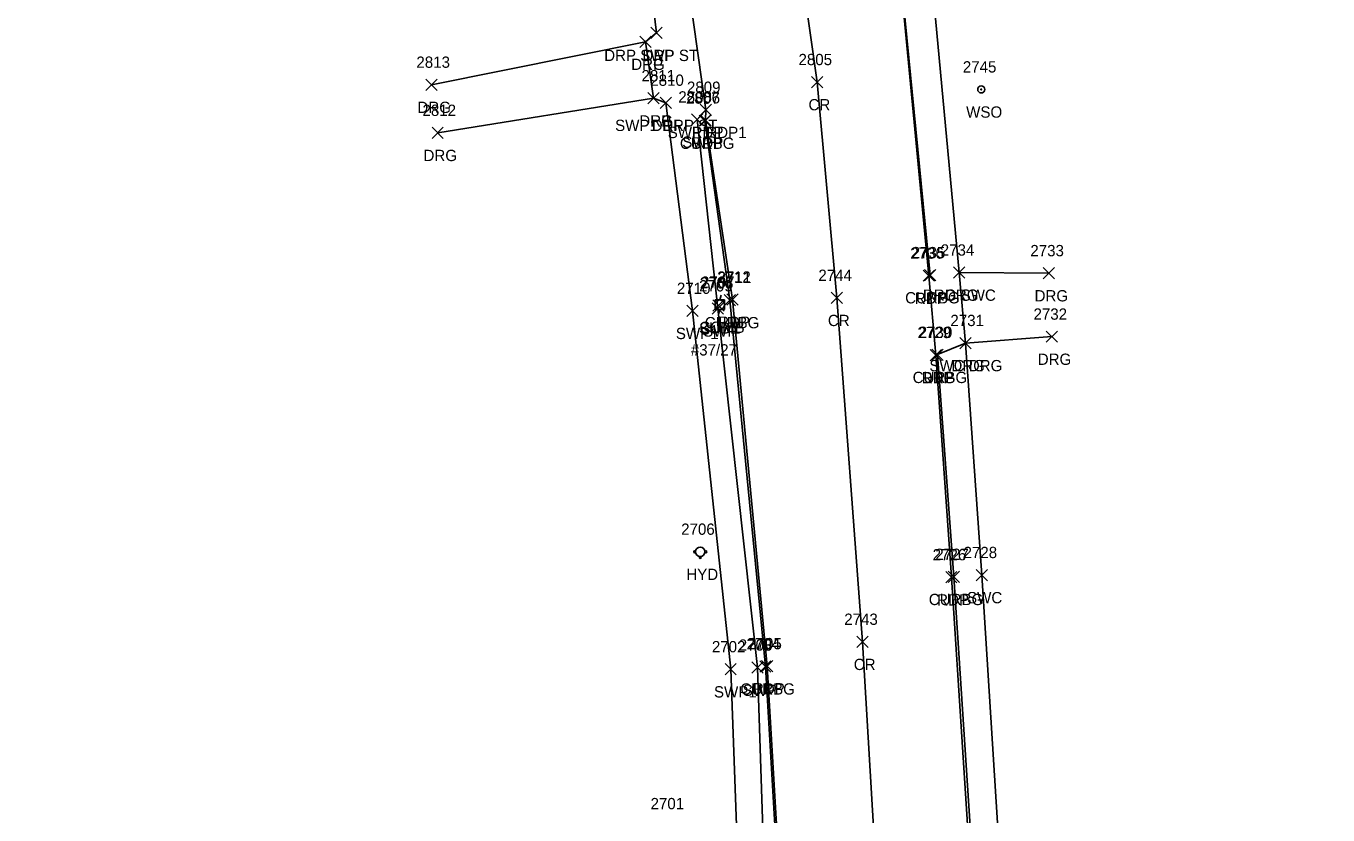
# Model space of a CAD drawing. Extents: x 1690689 to 1696275, y 438760 to 444007.
# Drawn here: x 1691078.4 to 1691309, y 441527.3 to 441667 of the extents above; entities that cross this region are included whole.
import ezdxf

# ---------------------------------------------------------------- set-up
doc = ezdxf.new("R2010")
doc.units = 0
for name, color, linetype in [('L_I', 7, 'Continuous'), ('P_A', 7, 'Continuous'), ('P_I', 7, 'Continuous'), ('P_TIC', 7, 'Continuous'), ('PET', 7, 'Continuous'), ('PRC', 7, 'Continuous'), ('R_A', 7, 'Continuous'), ('R_I', 7, 'Continuous'), ('R_TIC', 7, 'Continuous'), ('RC', 7, 'Continuous'), ('RDG', 7, 'Continuous'), ('RDP', 7, 'Continuous'), ('RSW', 7, 'Continuous'), ('U_A', 7, 'Continuous'), ('U_C', 7, 'Continuous'), ('U_I', 7, 'Continuous'), ('U_TIC', 7, 'Continuous'), ('UP', 7, 'Continuous'), ('UWFH', 7, 'Continuous'), ('UWV', 7, 'Continuous')]:
    doc.layers.add(name, color=color, linetype=linetype)

msp = doc.modelspace()

# ---------------------------------------------------------------- linework, layer by layer
at = {"layer": 'P_TIC'}
for points in [[(1691217.57, 441656.04), (1691219.57, 441658.04)], [(1691219.57, 441656.04), (1691217.57, 441658.04)], [(1691197.8, 441649.27), (1691199.8, 441651.27)], [(1691199.8, 441649.27), (1691197.8, 441651.27)], [(1691197.82, 441651.13), (1691199.82, 441653.13)], [(1691199.82, 441651.13), (1691197.82, 441653.13)], [(1691237.35, 441621.76), (1691239.35, 441623.76)], [(1691239.35, 441621.76), (1691237.35, 441623.76)], [(1691202.53, 441617.53), (1691204.53, 441619.53)], [(1691204.53, 441617.53), (1691202.53, 441619.53)], [(1691221.02, 441617.83), (1691223.02, 441619.83)], [(1691223.02, 441617.83), (1691221.02, 441619.83)], [(1691238.58, 441607.7), (1691240.58, 441609.7)], [(1691240.58, 441607.7), (1691238.58, 441609.7)], [(1691241.31, 441568.35), (1691243.31, 441570.35)], [(1691243.31, 441568.35), (1691241.31, 441570.35)], [(1691225.6, 441556.92), (1691227.6, 441558.92)], [(1691227.6, 441556.92), (1691225.6, 441558.92)], [(1691208.68, 441552.6), (1691210.68, 441554.6)], [(1691210.68, 441552.6), (1691208.68, 441554.6)]]:
    msp.add_lwpolyline(points, dxfattribs=at)
at = {"layer": 'PET'}
for points in [[(1691238.51, 441080.26), (1691233.04, 441128.02), (1691229.34, 441189.95), (1691225.2, 441266.32), (1691222.49, 441331.42), (1691221.87, 441352.01), (1691219.29, 441402.36), (1691215.78, 441404.57), (1691214.66, 441461.76), (1691212.86, 441499.57), (1691209.68, 441553.6), (1691203.53, 441618.53), (1691198.8, 441650.27), (1691198.82, 441652.13), (1691193.05, 441693.14)], [(1691309.01, 441068.57), (1691294.14, 441127.58), (1691279.71, 441186.12), (1691271.54, 441225.45), (1691269.6, 441237.09), (1691266.18, 441258.66), (1691260.33, 441297.66), (1691253.06, 441350.59), (1691250.02, 441376.37), (1691249.19, 441394.8), (1691248.99, 441398.05), (1691250.15, 441432.81), (1691248.61, 441468.02), (1691245.58, 441519.21), (1691242.31, 441569.35), (1691239.58, 441608.7), (1691238.35, 441622.76), (1691233.07, 441677.78)]]:
    msp.add_lwpolyline(points, dxfattribs=at)
at = {"layer": 'PRC'}
msp.add_lwpolyline([(1691277.81, 441080.96), (1691253.5, 441214.94), (1691246.19, 441267.52), (1691239.79, 441327.83), (1691235.79, 441375.29), (1691233.27, 441422.2), (1691229.73, 441505.18), (1691226.6, 441557.92), (1691222.02, 441618.83), (1691218.57, 441657.04), (1691144.02, 442182.42), (1691112.43, 442376.83), (1691097.75, 442454.48), (1691089.73, 442499.13), (1691078.44, 442565.84)], dxfattribs=at)
at = {"layer": 'R_TIC'}
for points in [[(1691187.13, 441663.19), (1691189.13, 441665.19)], [(1691189.13, 441663.19), (1691187.13, 441665.19)], [(1691187.13, 441663.19), (1691189.13, 441665.19)], [(1691189.13, 441663.19), (1691187.13, 441665.19)], [(1691189.11, 441664.77), (1691191.11, 441666.77)], [(1691191.11, 441664.77), (1691189.11, 441666.77)], [(1691189.11, 441664.77), (1691191.11, 441666.77)], [(1691191.11, 441664.77), (1691189.11, 441666.77)], [(1691149.27, 441655.57), (1691151.27, 441657.57)], [(1691151.27, 441655.57), (1691149.27, 441657.57)], [(1691188.56, 441653.17), (1691190.56, 441655.17)], [(1691190.56, 441653.17), (1691188.56, 441655.17)], [(1691188.56, 441653.17), (1691190.56, 441655.17)], [(1691190.56, 441653.17), (1691188.56, 441655.17)], [(1691190.76, 441652.38), (1691192.76, 441654.38)], [(1691192.76, 441652.38), (1691190.76, 441654.38)], [(1691190.76, 441652.38), (1691192.76, 441654.38)], [(1691192.76, 441652.38), (1691190.76, 441654.38)], [(1691196.3, 441649.42), (1691198.3, 441651.42)], [(1691198.3, 441649.42), (1691196.3, 441651.42)], [(1691197.66, 441649.21), (1691199.66, 441651.21)], [(1691199.66, 441649.21), (1691197.66, 441651.21)], [(1691197.82, 441651.13), (1691199.82, 441653.13)], [(1691199.82, 441651.13), (1691197.82, 441653.13)], [(1691150.34, 441647.05), (1691152.34, 441649.05)], [(1691152.34, 441647.05), (1691150.34, 441649.05)], [(1691237.55, 441621.85), (1691239.55, 441623.85)], [(1691239.55, 441621.85), (1691237.55, 441623.85)], [(1691242.69, 441622.31), (1691244.69, 441624.31)], [(1691244.69, 441622.31), (1691242.69, 441624.31)], [(1691242.69, 441622.31), (1691244.69, 441624.31)], [(1691244.69, 441622.31), (1691242.69, 441624.31)], [(1691258.56, 441622.2), (1691260.56, 441624.2)], [(1691260.56, 441622.2), (1691258.56, 441624.2)], [(1691202.06, 441617.44), (1691204.06, 441619.44)], [(1691204.06, 441617.44), (1691202.06, 441619.44)], [(1691195.48, 441615.53), (1691197.48, 441617.53)], [(1691197.48, 441615.53), (1691195.48, 441617.53)], [(1691199.98, 441615.97), (1691201.98, 441617.97)], [(1691201.98, 441615.97), (1691199.98, 441617.97)], [(1691243.84, 441609.83), (1691245.84, 441611.83)], [(1691245.84, 441609.83), (1691243.84, 441611.83)], [(1691243.84, 441609.83), (1691245.84, 441611.83)], [(1691245.84, 441609.83), (1691243.84, 441611.83)], [(1691259.12, 441610.96), (1691261.12, 441612.96)], [(1691261.12, 441610.96), (1691259.12, 441612.96)], [(1691238.58, 441607.7), (1691240.58, 441609.7)], [(1691240.58, 441607.7), (1691238.58, 441609.7)], [(1691238.88, 441607.74), (1691240.88, 441609.74)], [(1691240.88, 441607.74), (1691238.88, 441609.74)], [(1691241.73, 441568.42), (1691243.73, 441570.42)], [(1691243.73, 441568.42), (1691241.73, 441570.42)], [(1691246.73, 441568.74), (1691248.73, 441570.74)], [(1691248.73, 441568.74), (1691246.73, 441570.74)], [(1691202.23, 441552.06), (1691204.23, 441554.06)], [(1691204.23, 441552.06), (1691202.23, 441554.06)], [(1691207, 441552.35), (1691209, 441554.35)], [(1691209, 441552.35), (1691207, 441554.35)], [(1691208.37, 441552.57), (1691210.37, 441554.57)], [(1691210.37, 441552.57), (1691208.37, 441554.57)]]:
    msp.add_lwpolyline(points, dxfattribs=at)
at = {"layer": 'RC'}
for points in [[(1691238.55, 441622.85), (1691233.16, 441677.64), (1691233.32, 441686.72)], [(1691215.39, 441404.68), (1691215.44, 441414.13), (1691214.38, 441461.8), (1691213.04, 441486.91), (1691210.32, 441490.34), (1691210.36, 441496.03), (1691212.56, 441499.44), (1691209.37, 441553.57), (1691203.06, 441618.44), (1691198.66, 441650.21)], [(1691250.37, 441433.18), (1691248.85, 441468.05), (1691246.04, 441518.94), (1691242.73, 441569.42), (1691239.88, 441608.74)]]:
    msp.add_lwpolyline(points, dxfattribs=at)
at = {"layer": 'RDG'}
for points in [[(1691150.27, 441656.57), (1691188.13, 441664.19)], [(1691189.56, 441654.17), (1691151.34, 441648.05)], [(1691259.56, 441623.2), (1691243.69, 441623.31)], [(1691239.58, 441608.7), (1691244.84, 441610.83), (1691260.12, 441611.96)]]:
    msp.add_lwpolyline(points, dxfattribs=at)
at = {"layer": 'RDP'}
msp.add_lwpolyline([(1691191.76, 441653.38), (1691189.56, 441654.17), (1691188.13, 441664.19), (1691190.11, 441665.77)], dxfattribs=at)
at = {"layer": 'RSW'}
for points in [[(1691255.61, 441432.95), (1691254.04, 441468.48), (1691250.9, 441519.29), (1691247.73, 441569.74), (1691244.84, 441610.83), (1691243.69, 441623.31), (1691238.63, 441677.88), (1691238.56, 441689.61), (1691238.46, 441702.13), (1691241.2, 441724.33)], [(1691190.11, 441665.77), (1691188.92, 441675.54)], [(1691208.67, 441413.74), (1691206.69, 441461.6), (1691205.25, 441497.77), (1691203.23, 441553.06), (1691196.48, 441616.53), (1691191.76, 441653.38)], [(1691210.36, 441496.03), (1691209.79, 441497.9), (1691208, 441553.35), (1691200.98, 441616.97), (1691197.3, 441650.42), (1691198.82, 441652.13)]]:
    msp.add_lwpolyline(points, dxfattribs=at)
at = {"layer": 'U_TIC'}
for points in [[(1691200.1, 441616.49), (1691202.1, 441618.49)], [(1691202.1, 441616.49), (1691200.1, 441618.49)]]:
    msp.add_lwpolyline(points, dxfattribs=at)
at = {"layer": 'UP'}
for p, q in [((1691201.56, 441619.29), (1691201.31, 441618.46)), ((1691200.48, 441616.79), (1691200.48, 441618.46)), ((1691200.48, 441618.46), (1691202.14, 441618.46)), ((1691202.14, 441616.79), (1691200.48, 441616.79)), ((1691201.06, 441615.96), (1691201.31, 441616.79)), ((1691201.31, 441617.62), (1691201.31, 441617.62)), ((1691202.14, 441618.46), (1691202.14, 441616.79))]:
    msp.add_line(p, q, dxfattribs=at)
msp.add_circle((1691201.31, 441617.62), 0.833, dxfattribs=at)
at = {"layer": 'UWFH'}
msp.add_line((1691197.85, 441573.87), (1691197.85, 441573.87), dxfattribs=at)
for centre, radius in [((1691196.85, 441573.87), 0.167), ((1691197.85, 441573.87), 0.833), ((1691197.85, 441572.87), 0.167), ((1691198.85, 441573.87), 0.167)]:
    msp.add_circle(centre, radius, dxfattribs=at)
at = {"layer": 'UWV'}
for radius in [0.625, 0.0833]:
    msp.add_circle((1691247.6, 441655.74), radius, dxfattribs=at)

# ---------------------------------------------------------------- texts
at = {"layer": 'L_I'}
msp.add_text('2701', height=2, dxfattribs=at).set_placement((1691189.04, 441528.27))
at = {"layer": 'P_A'}
for s, p in [('CR', (1691217.01, 441652.04)), ('RDP', (1691196.31, 441647.13)), ('RDP', (1691196.28, 441645.27)), ('RDP', (1691235.84, 441617.76)), ('RDP', (1691201.02, 441613.53)), ('CR', (1691220.45, 441613.83)), ('RDP', (1691237.07, 441603.7)), ('RDP', (1691239.8, 441564.35)), ('CR', (1691225.03, 441552.92)), ('RDP', (1691207.16, 441548.6))]:
    msp.add_text(s, height=2, dxfattribs=at).set_placement(p)
at = {"layer": 'P_I'}
for s, p in [('2805', (1691215.24, 441660.04)), ('2809', (1691195.48, 441655.13)), ('2806', (1691195.4, 441653.27)), ('2736', (1691235.03, 441625.76)), ('2712', (1691200.84, 441621.53)), ('2744', (1691218.76, 441621.83)), ('2729', (1691236.31, 441611.7)), ('2726', (1691239, 441572.35)), ('2743', (1691223.34, 441560.92)), ('2705', (1691206.34, 441556.6))]:
    msp.add_text(s, height=2, dxfattribs=at).set_placement(p)
at = {"layer": 'R_A'}
for s, p in [('DRP SWP ST', (1691180.83, 441660.77)), ('DRP', (1691187.6, 441660.77)), ('DRG', (1691185.62, 441659.19)), ('DRP', (1691185.62, 441659.19)), ('DRG', (1691147.75, 441651.57)), ('DRG', (1691187.05, 441649.17)), ('DRP', (1691187.05, 441649.17)), ('SWP1 DRP ST', (1691182.76, 441648.38)), ('DRP', (1691189.25, 441648.38)), ('SWP RDP1', (1691192.08, 441647.13)), ('CURBG', (1691194.24, 441645.21)), ('SWP', (1691194.66, 441645.42)), ('DRG', (1691148.83, 441643.05)), ('CURBG', (1691234.13, 441617.85)), ('DRG SWC', (1691237.27, 441618.31)), ('DRG', (1691241.17, 441618.31)), ('DRG', (1691257.05, 441618.2)), ('SWP', (1691198.34, 441611.97)), ('CURBG', (1691198.65, 441613.44)), ('SWP1', (1691193.52, 441611.53)), ('SWC DRG', (1691238.42, 441605.83)), ('DRG', (1691242.32, 441605.83)), ('DRG', (1691257.61, 441606.96)), ('CURBG', (1691235.46, 441603.74)), ('DRG', (1691237.07, 441603.7)), ('CURBG', (1691238.32, 441564.42)), ('SWC', (1691245.09, 441564.74)), ('SWP1', (1691200.27, 441548.06)), ('CURBG', (1691204.95, 441548.57)), ('SWP', (1691205.36, 441548.35))]:
    msp.add_text(s, height=2, dxfattribs=at).set_placement(p)
at = {"layer": 'R_I'}
for s, p in [('2813', (1691147.57, 441659.57)), ('2811', (1691187.44, 441657.17)), ('2811', (1691187.44, 441657.17)), ('2810', (1691188.99, 441656.38)), ('2810', (1691188.99, 441656.38)), ('2809', (1691195.48, 441655.13)), ('2808', (1691193.96, 441653.42)), ('2807', (1691195.32, 441653.21)), ('2812', (1691148.65, 441651.05)), ('2735', (1691235.29, 441625.85)), ('2734', (1691240.43, 441626.31)), ('2734', (1691240.43, 441626.31)), ('2733', (1691256.3, 441626.2)), ('2711', (1691200.94, 441621.44)), ('2710', (1691193.7, 441619.53)), ('2709', (1691197.64, 441619.97)), ('2732', (1691256.86, 441614.96)), ('2731', (1691242.14, 441613.83)), ('2731', (1691242.14, 441613.83)), ('2729', (1691236.31, 441611.7)), ('2730', (1691236.53, 441611.74)), ('2727', (1691239.47, 441572.42)), ('2728', (1691244.47, 441572.74)), ('2702', (1691199.9, 441556.06)), ('2703', (1691204.66, 441556.35)), ('2704', (1691206.03, 441556.57))]:
    msp.add_text(s, height=2, dxfattribs=at).set_placement(p)
at = {"layer": 'U_A'}
for s, p in [('WSO', (1691244.93, 441650.74)), ('SUBE', (1691197.63, 441612.49)), ('COMB', (1691197.69, 441612.62)), ('HYD', (1691195.37, 441568.87))]:
    msp.add_text(s, height=2, dxfattribs=at).set_placement(p)
at = {"layer": 'U_C'}
msp.add_text('#37/27', height=2, dxfattribs=at).set_placement((1691196.17, 441608.62))
at = {"layer": 'U_I'}
for s, p in [('2745', (1691244.34, 441658.74)), ('2708', (1691197.76, 441620.49)), ('2707', (1691197.97, 441620.62)), ('2706', (1691194.46, 441576.87))]:
    msp.add_text(s, height=2, dxfattribs=at).set_placement(p)

doc.saveas('drawing.dxf')
